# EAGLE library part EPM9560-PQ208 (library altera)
EPM9560 MAX 9000 family
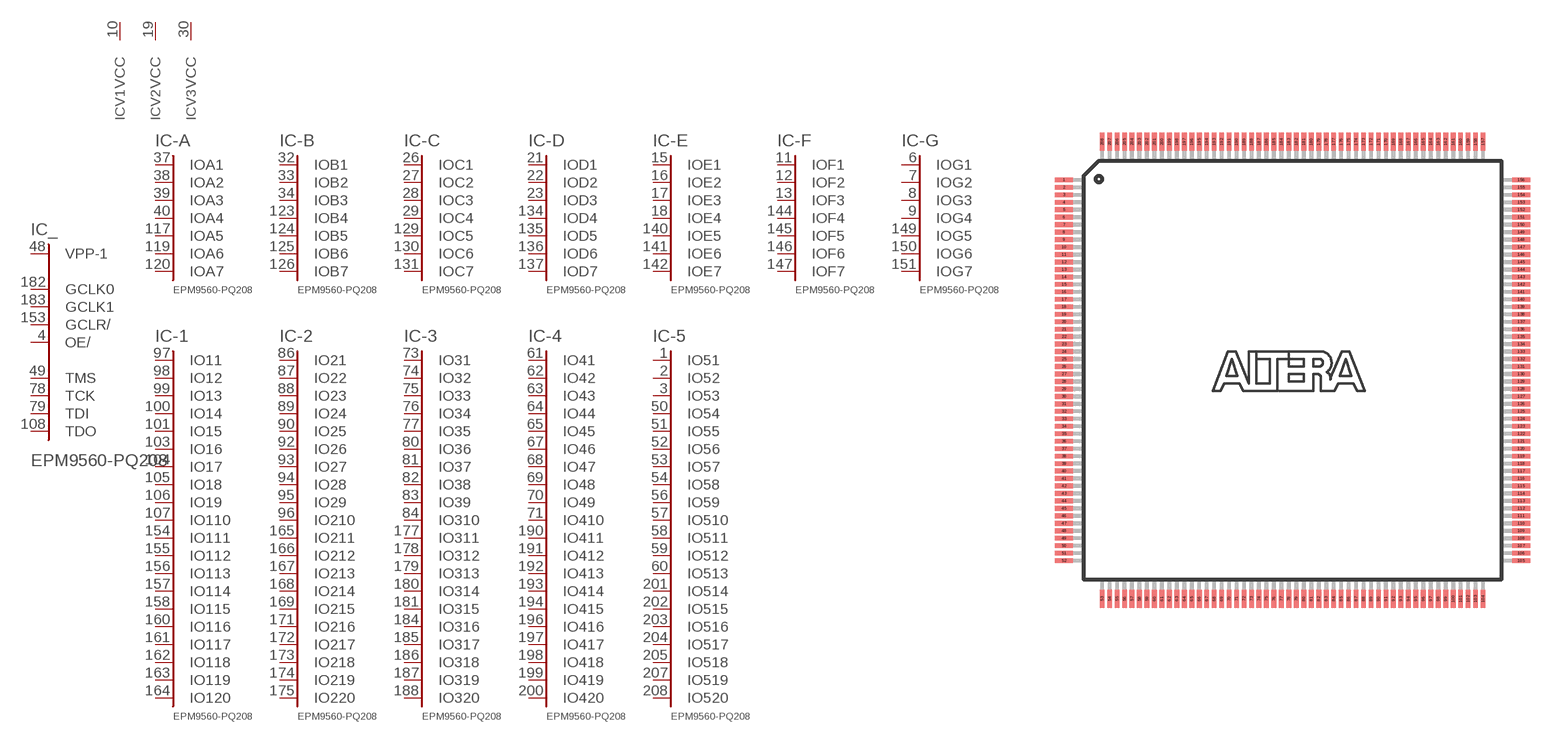
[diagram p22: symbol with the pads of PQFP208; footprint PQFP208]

Designator prefix IC; gates _=9560C356 -A=A7 -B=B7 -C=C7 -D=D7 -E=E7 -F=F7 -G=G7 -1=IO120 -2=IO220 -3=IO320 -4=IO420 -5=IO520 V1=VCCINT V2=VCCINT V3=VCCINT V4=VCCINT V5=VCCINT V6=VCCINT V7=VCCINT V8=VCCINT VO1=VCCIO VO2=VCCIO VO3=VCCIO VO4=VCCIO VO5=VCCIO VO6=VCCIO VO7=VCCIO VO8=VCCIO VO9=VCCIO VO10=VCCIO VO11=VCCIO VO12=VCCIO G1=GND G2=GND G3=GND G4=GND G5=GND G6=GND G7=GND G8=GND G9=GND G10=GND G11=GND G12=GND G13=GND G14=GND G15=GND G16=GND G17=GND G18=GND G19=GND G20=GND G21=GND G22=GND G23=GND G24=GND G25=GND G26=GND G27=GND G28=GND G29=GND NC1=NC

## EPM9560-PQ208 (MPN: EPM9560ARC208-10; OC_FARNELL: unknown; OC_NEWARK: 51R9961)  [PQFP208]
1  -5:IO51
2  -5:IO52
3  -5:IO53
4  _:OE/  in
5  VO1:VCCIO  pwr
6  -G:IOG1
7  -G:IOG2
8  -G:IOG3
9  -G:IOG4
10  V1:VCC  pwr
11  -F:IOF1
12  -F:IOF2
13  -F:IOF3
14  G1:GND  pwr
15  -E:IOE1
16  -E:IOE2
17  -E:IOE3
18  -E:IOE4
19  V2:VCC  pwr
20  G2:GND  pwr
21  -D:IOD1
22  -D:IOD2
23  -D:IOD3
24  G3:GND  pwr
25  VO2:VCCIO  pwr
26  -C:IOC1
27  -C:IOC2
28  -C:IOC3
29  -C:IOC4
30  V3:VCC  pwr
31  G4:GND  pwr
32  -B:IOB1
33  -B:IOB2
34  -B:IOB3
35  G5:GND  pwr
36  VO3:VCCIO  pwr
37  -A:IOA1
38  -A:IOA2
39  -A:IOA3
40  -A:IOA4
41  G6:GND  pwr
42  G7:GND  pwr
43  G8:GND  pwr
44  G9:GND  pwr
45  V4:VCC  pwr
46  G10:GND  pwr
47  G11:GND  pwr
48  _:VPP-1  in
49  _:TMS
50  -5:IO54
51  -5:IO55
52  -5:IO56
53  -5:IO57
54  -5:IO58
55  VO4:VCCIO  pwr
56  -5:IO59
57  -5:IO510
58  -5:IO511
59  -5:IO512
60  -5:IO513
61  -4:IO41
62  -4:IO42
63  -4:IO43
64  -4:IO44
65  -4:IO45
66  G12:GND  pwr
67  -4:IO46
68  -4:IO47
69  -4:IO48
70  -4:IO49
71  -4:IO410
72  VO5:VCCIO  pwr
73  -3:IO31
74  -3:IO32
75  -3:IO33
76  -3:IO34
77  -3:IO35
78  _:TCK
79  _:TDI
80  -3:IO36
81  -3:IO37
82  -3:IO38
83  -3:IO39
84  -3:IO310
85  G13:GND  pwr
86  -2:IO21
87  -2:IO22
88  -2:IO23
89  -2:IO24
90  -2:IO25
91  VO6:VCCIO  pwr
92  -2:IO26
93  -2:IO27
94  -2:IO28
95  -2:IO29
96  -2:IO210
97  -1:IO11
98  -1:IO12
99  -1:IO13
100  -1:IO14
101  -1:IO15
102  G14:GND  pwr
103  -1:IO16
104  -1:IO17
105  -1:IO18
106  -1:IO19
107  -1:IO110
108  _:TDO
109  NC1:NC  nc
110  G15:GND  pwr
111  VO7:VCCIO  pwr
112  V5:VCC  pwr
113  G16:GND  pwr
114  G17:GND  pwr
115  G18:GND  pwr
116  G19:GND  pwr
117  -A:IOA5
118  G20:GND  pwr
119  -A:IOA6
120  -A:IOA7
121  G21:GND  pwr
122  G22:GND  pwr
123  -B:IOB4
124  -B:IOB5
125  -B:IOB6
126  -B:IOB7
127  VO8:VCCIO  pwr
128  V6:VCC  pwr
129  -C:IOC5
130  -C:IOC6
131  -C:IOC7
132  G23:GND  pwr
133  G24:GND  pwr
134  -D:IOD4
135  -D:IOD5
136  -D:IOD6
137  -D:IOD7
138  VO9:VCCIO  pwr
139  V7:VCC  pwr
140  -E:IOE5
141  -E:IOE6
142  -E:IOE7
143  G25:GND  pwr
144  -F:IOF4
145  -F:IOF5
146  -F:IOF6
147  -F:IOF7
148  V8:VCC  pwr
149  -G:IOG5
150  -G:IOG6
151  -G:IOG7
152  G26:GND  pwr
153  _:GCLR/  in
154  -1:IO111
155  -1:IO112
156  -1:IO113
157  -1:IO114
158  -1:IO115
159  VO10:VCCIO  pwr
160  -1:IO116
161  -1:IO117
162  -1:IO118
163  -1:IO119
164  -1:IO120
165  -2:IO211
166  -2:IO212
167  -2:IO213
168  -2:IO214
169  -2:IO215
170  G27:GND  pwr
171  -2:IO216
172  -2:IO217
173  -2:IO218
174  -2:IO219
175  -2:IO220
176  VO11:VCCIO  pwr
177  -3:IO311
178  -3:IO312
179  -3:IO313
180  -3:IO314
181  -3:IO315
182  _:GCLK0  in
183  _:GCLK1  in
184  -3:IO316
185  -3:IO317
186  -3:IO318
187  -3:IO319
188  -3:IO320
189  G28:GND  pwr
190  -4:IO411
191  -4:IO412
192  -4:IO413
193  -4:IO414
194  -4:IO415
195  VO12:VCCIO  pwr
196  -4:IO416
197  -4:IO417
198  -4:IO418
199  -4:IO419
200  -4:IO420
201  -5:IO514
202  -5:IO515
203  -5:IO516
204  -5:IO517
205  -5:IO518
206  G29:GND  pwr
207  -5:IO519
208  -5:IO520

## Footprint PQFP208 (pad centres in mm)
Plastic Quad Flat Pack
smd 1.2 x 0.32: 1 -15.3,12.75; 2 -15.3,12.25; 3 -15.3,11.75; 4 -15.3,11.25; 5 -15.3,10.75; 6 -15.3,10.25; 7 -15.3,9.75; 8 -15.3,9.25; 9 -15.3,8.75; 10 -15.3,8.25; 11 -15.3,7.75; 12 -15.3,7.25; 13 -15.3,6.75; 14 -15.3,6.25; 15 -15.3,5.75; 16 -15.3,5.25; 17 -15.3,4.75; 18 -15.3,4.25; 19 -15.3,3.75; 20 -15.3,3.25; 21 -15.3,2.75; 22 -15.3,2.25; 23 -15.3,1.75; 24 -15.3,1.25; 25 -15.3,0.75; 26 -15.3,0.25; 27 -15.3,-0.25; 28 -15.3,-0.75; 29 -15.3,-1.25; 30 -15.3,-1.75; 31 -15.3,-2.25; 32 -15.3,-2.75; 33 -15.3,-3.25; 34 -15.3,-3.75; 35 -15.3,-4.25; 36 -15.3,-4.75; 37 -15.3,-5.25; 38 -15.3,-5.75; 39 -15.3,-6.25; 40 -15.3,-6.75; 41 -15.3,-7.25; 42 -15.3,-7.75; 43 -15.3,-8.25; 44 -15.3,-8.75; 45 -15.3,-9.25; 46 -15.3,-9.75; 47 -15.3,-10.25; 48 -15.3,-10.75; 49 -15.3,-11.25; 50 -15.3,-11.75; 51 -15.3,-12.25; 52 -15.3,-12.75; 105 15.3,-12.75; 106 15.3,-12.25; 107 15.3,-11.75; 108 15.3,-11.25; 109 15.3,-10.75; 110 15.3,-10.25; 111 15.3,-9.75; 112 15.3,-9.25; 113 15.3,-8.75; 114 15.3,-8.25; 115 15.3,-7.75; 116 15.3,-7.25; 117 15.3,-6.75; 118 15.3,-6.25; 119 15.3,-5.75; 120 15.3,-5.25; 121 15.3,-4.75; 122 15.3,-4.25; 123 15.3,-3.75; 124 15.3,-3.25; 125 15.3,-2.75; 126 15.3,-2.25; 127 15.3,-1.75; 128 15.3,-1.25; 129 15.3,-0.75; 130 15.3,-0.25; 131 15.3,0.25; 132 15.3,0.75; 133 15.3,1.25; 134 15.3,1.75; 135 15.3,2.25; 136 15.3,2.75; 137 15.3,3.25; 138 15.3,3.75; 139 15.3,4.25; 140 15.3,4.75; 141 15.3,5.25; 142 15.3,5.75; 143 15.3,6.25; 144 15.3,6.75; 145 15.3,7.25; 146 15.3,7.75; 147 15.3,8.25; 148 15.3,8.75; 149 15.3,9.25; 150 15.3,9.75; 151 15.3,10.25; 152 15.3,10.75; 153 15.3,11.25; 154 15.3,11.75; 155 15.3,12.25; 156 15.3,12.75
smd 0.32 x 1.2: 53 -12.75,-15.3; 54 -12.25,-15.3; 55 -11.75,-15.3; 56 -11.25,-15.3; 57 -10.75,-15.3; 58 -10.25,-15.3; 59 -9.75,-15.3; 60 -9.25,-15.3; 61 -8.75,-15.3; 62 -8.25,-15.3; 63 -7.75,-15.3; 64 -7.25,-15.3; 65 -6.75,-15.3; 66 -6.25,-15.3; 67 -5.75,-15.3; 68 -5.25,-15.3; 69 -4.75,-15.3; 70 -4.25,-15.3; 71 -3.75,-15.3; 72 -3.25,-15.3; 73 -2.75,-15.3; 74 -2.25,-15.3; 75 -1.75,-15.3; 76 -1.25,-15.3; 77 -0.75,-15.3; 78 -0.25,-15.3; 79 0.25,-15.3; 80 0.75,-15.3; 81 1.25,-15.3; 82 1.75,-15.3; 83 2.25,-15.3; 84 2.75,-15.3; 85 3.25,-15.3; 86 3.75,-15.3; 87 4.25,-15.3; 88 4.75,-15.3; 89 5.25,-15.3; 90 5.75,-15.3; 91 6.25,-15.3; 92 6.75,-15.3; 93 7.25,-15.3; 94 7.75,-15.3; 95 8.25,-15.3; 96 8.75,-15.3; 97 9.25,-15.3; 98 9.75,-15.3; 99 10.25,-15.3; 100 10.75,-15.3; 101 11.25,-15.3; 102 11.75,-15.3; 103 12.25,-15.3; 104 12.75,-15.3; 157 12.75,15.3; 158 12.25,15.3; 159 11.75,15.3; 160 11.25,15.3; 161 10.75,15.3; 162 10.25,15.3; 163 9.75,15.3; 164 9.25,15.3; 165 8.75,15.3; 166 8.25,15.3; 167 7.75,15.3; 168 7.25,15.3; 169 6.75,15.3; 170 6.25,15.3; 171 5.75,15.3; 172 5.25,15.3; 173 4.75,15.3; 174 4.25,15.3; 175 3.75,15.3; 176 3.25,15.3; 177 2.75,15.3; 178 2.25,15.3; 179 1.75,15.3; 180 1.25,15.3; 181 0.75,15.3; 182 0.25,15.3; 183 -0.25,15.3; 184 -0.75,15.3; 185 -1.25,15.3; 186 -1.75,15.3; 187 -2.25,15.3; 188 -2.75,15.3; 189 -3.25,15.3; 190 -3.75,15.3; 191 -4.25,15.3; 192 -4.75,15.3; 193 -5.25,15.3; 194 -5.75,15.3; 195 -6.25,15.3; 196 -6.75,15.3; 197 -7.25,15.3; 198 -7.75,15.3; 199 -8.25,15.3; 200 -8.75,15.3; 201 -9.25,15.3; 202 -9.75,15.3; 203 -10.25,15.3; 204 -10.75,15.3; 205 -11.25,15.3; 206 -11.75,15.3; 207 -12.25,15.3; 208 -12.75,15.3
